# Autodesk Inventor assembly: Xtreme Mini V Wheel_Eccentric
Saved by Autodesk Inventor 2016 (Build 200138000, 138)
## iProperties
Created: 2016-03
Part Number: Xtreme Mini V Wheel_Eccentric
Document SubType Name: Assembly
Designer: bongo_000
Author: bongo_000
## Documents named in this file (6)
- C:\Users\bongo_000\Downloads\DLP\Xtreme Mini V Wheel_Eccentric.iam
- C:\Users\bongo_000\Downloads\DLP\Precision Shim 8 x 5 x 1.ipt
- C:\Users\bongo_000\Downloads\DLP\Xtreme Mini V Wheel.ipt
- C:\Users\bongo_000\Downloads\DLP\Mini Eccentric Spacer 6mm.ipt
- C:\Users\bongo_000\Downloads\DLP\Ball Bearing 5 x 10 x 4.2.ipt
- C:\Users\bongo_000\Downloads\DLP\Nylon Insert Lock Nut M5.ipt
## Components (7 placed, 7 different names)
1. Precision Shim 8 x 5 x 1_1014
2. Xtreme Mini V Wheel_1015
3. Precision Shim 8 x 5 x 1_1016
4. Mini Eccentric Spacer 6mm_1017
5. Ball Bearing 5 x 10 x 4.2_1018
6. Nylon Insert Lock Nut M5_1019
7. Ball Bearing 5 x 10 x 4.2_1020
